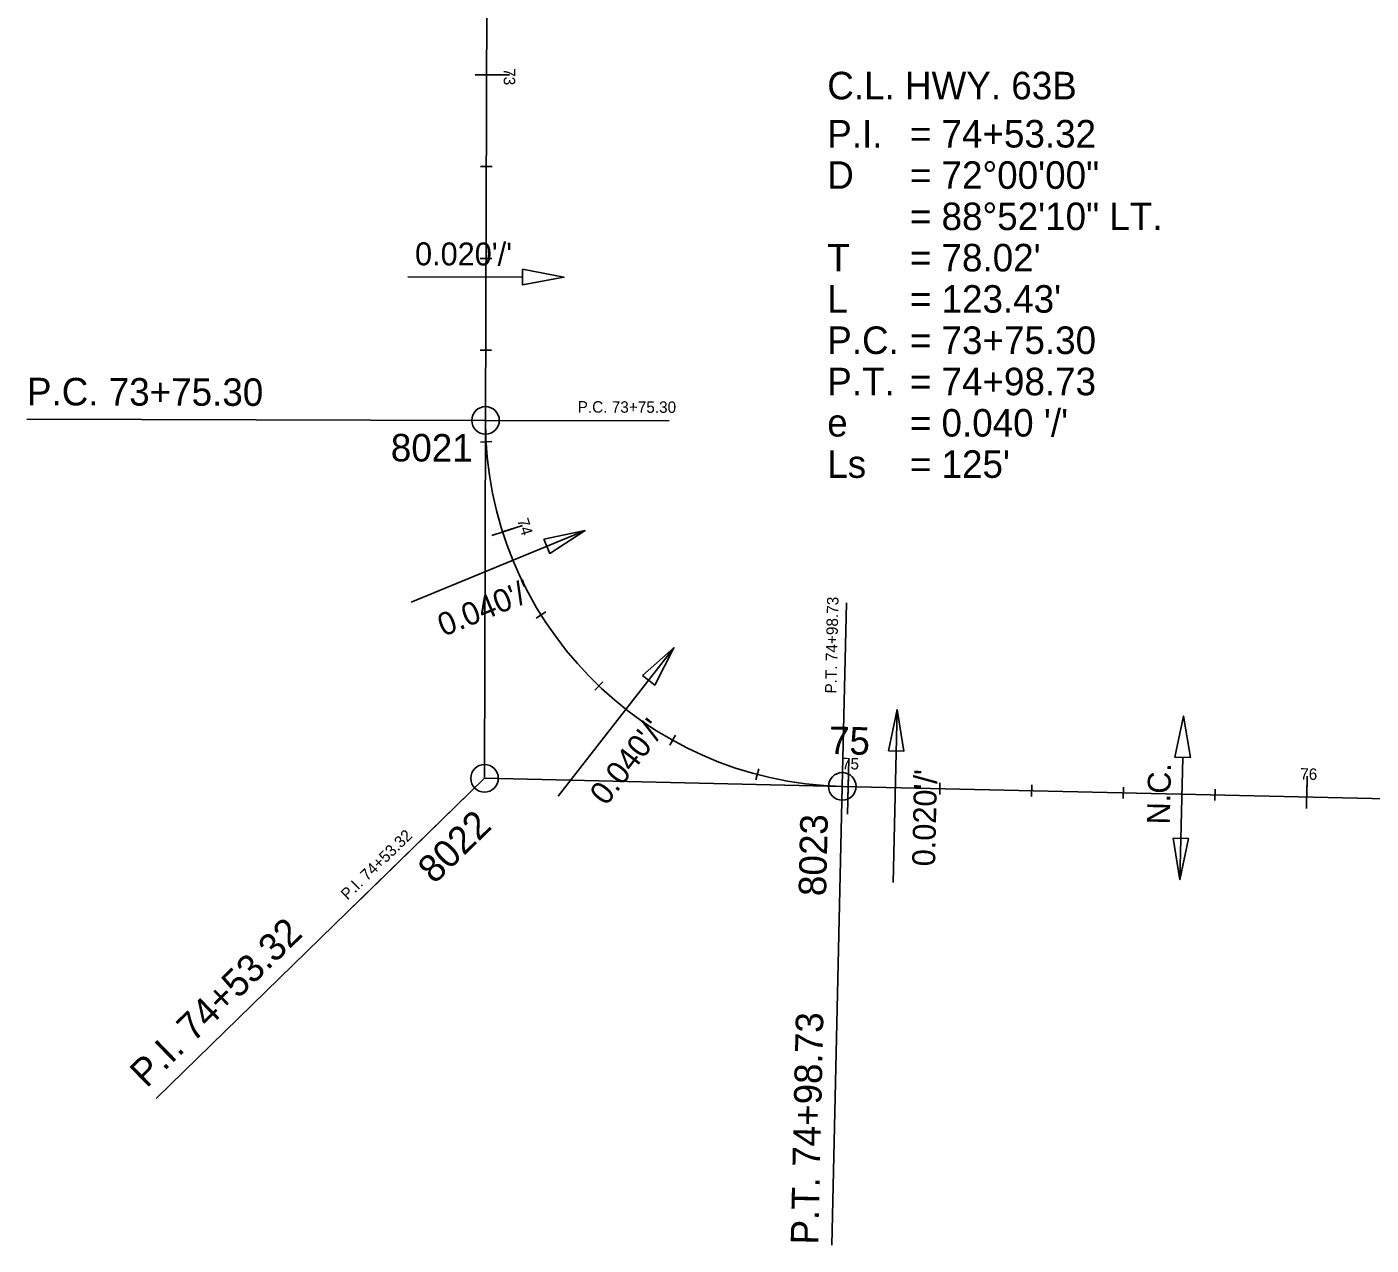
# Model space of a CAD drawing. Extents: x 1708585 to 1714116, y 541444 to 545437.
# Drawn here: x 1711889.1 to 1712182.2, y 543264.6 to 543530.1 of the extents above; entities that cross this region are included whole.
import ezdxf

# ---------------------------------------------------------------- set-up
doc = ezdxf.new("R2010")
doc.units = 0
for name, color, linetype in [('CL_Highway_2', 7, 'Continuous'), ('CL_Highway_2_40_PText', 7, 'Continuous'), ('CL_Highway_2_40_Sta', 7, 'Continuous'), ('CL_Highway_2_PText', 7, 'Continuous'), ('CL_Highway_2_Sta', 7, 'Continuous'), ('CL_Highway_2_Tangent', 7, 'Continuous'), ('CurveData_100', 7, 'Continuous'), ('Point_CL_Highway_2', 7, 'Continuous'), ('Point_Number', 7, 'Continuous'), ('R_SE_Slope', 7, 'Continuous')]:
    doc.layers.add(name, color=color, linetype=linetype)

msp = doc.modelspace()

# ---------------------------------------------------------------- linework, layer by layer
at = {"layer": 'CL_Highway_2'}
for p, q in [((1711989.93, 543735.39), (1711989.1, 543444.38)), ((1712066.88, 543364.6), (1712214.97, 543361.25))]:
    msp.add_line(p, q, dxfattribs=at)
msp.add_arc((1712068.68, 543444.15), 79.58, 179.8364, 268.7057, dxfattribs=at)
at = {"layer": 'CL_Highway_2_40_PText'}
for points in [[(1711989.1, 543444.38), (1712029.1, 543444.27)], [(1712066.88, 543364.6), (1712067.78, 543404.59)], [(1711988.88, 543366.36), (1711960.24, 543338.44)]]:
    msp.add_lwpolyline(points, dxfattribs=at)
at = {"layer": 'CL_Highway_2_40_Sta'}
for points in [[(1711991.81, 543519.67), (1711986.81, 543519.69)], [(1711990.51, 543499.68), (1711988.01, 543499.69)], [(1711990.45, 543479.68), (1711987.95, 543479.69)], [(1711990.39, 543459.68), (1711987.89, 543459.69)], [(1711990.47, 543439.75), (1711987.98, 543439.61)], [(1711995.22, 543420.82), (1711990.45, 543419.31)], [(1712002.27, 543402.62), (1712000.15, 543401.3)], [(1712014.68, 543387.41), (1712012.96, 543385.6)], [(1712030.49, 543375.77), (1712029.27, 543373.58)], [(1712048.69, 543368.42), (1712048.06, 543366)], [(1712068.2, 543367.07), (1712068.09, 543362.07)], [(1712088.17, 543365.37), (1712088.11, 543362.87)], [(1712108.17, 543364.91), (1712108.11, 543362.41)], [(1712168.18, 543364.81), (1712168.07, 543359.81)], [(1712128.16, 543364.46), (1712128.1, 543361.96)], [(1712148.16, 543364.01), (1712148.1, 543361.51)]]:
    msp.add_lwpolyline(points, dxfattribs=at)
at = {"layer": 'CL_Highway_2_PText'}
for points in [[(1711989.1, 543444.38), (1711889.1, 543444.67)], [(1711988.88, 543366.36), (1711917.27, 543296.55)], [(1712066.88, 543364.6), (1712064.62, 543264.62)]]:
    msp.add_lwpolyline(points, dxfattribs=at)
at = {"layer": 'CL_Highway_2_Sta'}
for p, q in [((1711994.31, 543519.67), (1711989.31, 543519.68)), ((1712068.28, 543370.57), (1712068.01, 543358.57))]:
    msp.add_line(p, q, dxfattribs=at)
for points in [[(1711997.12, 543421.43), (1711992.83, 543420.07)], [(1712168.22, 543366.81), (1712168.12, 543362.31)]]:
    msp.add_lwpolyline(points, dxfattribs=at)
at = {"layer": 'CL_Highway_2_Tangent'}
msp.add_lwpolyline([(1711989.1, 543444.38), (1711988.88, 543366.36), (1712066.88, 543364.6)], dxfattribs=at)
at = {"layer": 'Point_CL_Highway_2'}
for centre in [(1711989.1, 543444.38), (1711988.88, 543366.36), (1712066.88, 543364.6)]:
    msp.add_circle(centre, 3, dxfattribs=at)
at = {"layer": 'R_SE_Slope'}
for p, q in [((1711972.19, 543475.68), (1711997.19, 543475.61)), ((1711972.87, 543404.79), (1712010.79, 543420.37)), ((1712004.95, 543362.5), (1712030.17, 543394.82)), ((1712077.97, 543343.63), (1712078.82, 543381.33)), ((1712140.5, 543344.26), (1712141.1, 543370.92))]:
    msp.add_line(p, q, dxfattribs=at)
for points in [[(1711997.19, 543477.3), (1711997.18, 543473.92), (1712006.19, 543475.58)], [(1712001.83, 543418.51), (1712003.11, 543415.39), (1712010.79, 543420.37)], [(1712023.31, 543388.77), (1712025.97, 543386.69), (1712030.17, 543394.82)], [(1712076.93, 543372.37), (1712080.3, 543372.3), (1712078.82, 543381.33)], [(1712139.41, 543370.96), (1712142.79, 543370.88), (1712141.3, 543379.92)], [(1712142.39, 543353.22), (1712139.01, 543353.29), (1712140.5, 543344.26)]]:
    msp.add_lwpolyline(points, close=True, dxfattribs=at)

# ---------------------------------------------------------------- texts
at = {"layer": 'CL_Highway_2_40_PText'}
for s, rotation, p in [('P.C. 73+75.30', 359.8364, (1712009.18, 543446.07)), ('P.T. 74+98.73', 88.7057, (1712065.59, 543384.82)), ('P.I. 74+53.32', 44.2711, (1711959.01, 543339.69))]:
    msp.add_text(s, height=2.5, rotation=rotation, dxfattribs=at).set_placement(p)
at = {"layer": 'CL_Highway_2_40_Sta'}
for s, rotation, p in [('73', 269.8364, (1711993.07, 543521.14)), ('74', 287.6196, (1711995.96, 543422.6)), ('75', 358.7057, (1712066.77, 543368.35)), ('76', 358.7057, (1712166.69, 543366.09))]:
    msp.add_text(s, height=2.5, rotation=rotation, dxfattribs=at).set_placement(p)
at = {"layer": 'CL_Highway_2_PText'}
for s, rotation, p in [('P.C. 73+75.30', 359.8364, (1711889.11, 543447.67)), ('P.I. 74+53.32', 44.2711, (1711915.18, 543298.7)), ('P.T. 74+98.73', 88.7057, (1712061.62, 543264.69))]:
    msp.add_text(s, height=6, rotation=rotation, dxfattribs=at).set_placement(p)
at = {"layer": 'CL_Highway_2_Sta'}
msp.add_text('75', height=6, rotation=358.7057, dxfattribs=at).set_placement((1712063.91, 543371.67))
at = {"layer": 'CurveData_100'}
for s, p in [('C.L. HWY. 63B', (1712063.6, 543514.35)), ('P.I.', (1712063.6, 543503.85)), ('= 74+53.32', (1712081.6, 543503.85)), ('D', (1712063.6, 543494.85)), ('= 72%%d00\'00"', (1712081.6, 543494.85)), ('= 88%%d52\'10" LT.', (1712081.6, 543485.85)), ('T', (1712063.6, 543476.85)), ("= 78.02'", (1712081.6, 543476.85)), ('L', (1712063.6, 543467.85)), ("= 123.43'", (1712081.6, 543467.85)), ('P.C.', (1712063.6, 543458.85)), ('= 73+75.30', (1712081.6, 543458.85)), ('P.T.', (1712063.6, 543449.85)), ('= 74+98.73', (1712081.6, 543449.85)), ("= 0.040 '/'", (1712081.6, 543440.85)), ('e', (1712063.6, 543440.85)), ('Ls', (1712063.6, 543431.85)), ("= 125'", (1712081.6, 543431.85))]:
    msp.add_text(s, height=6, dxfattribs=at).set_placement(p)
at = {"layer": 'Point_Number'}
for s, rotation, p in [('8021', 359.8364, (1711968.44, 543435.44)), ('8022', 44.2711, (1711977.95, 543343.14)), ('8023', 88.7057, (1712063.34, 543340.64))]:
    msp.add_text(s, height=6, rotation=rotation, dxfattribs=at).set_placement(p)
at = {"layer": 'R_SE_Slope'}
for s, rotation, p in [("0.020'/'", 359.8364, (1711973.72, 543478.18)), ("0.040'/'", 22.3356, (1711979.95, 543397.18)), ("0.040'/'", 52.0284, (1712015.37, 543360.18)), ("0.020'/'", 88.7057, (1712087.09, 543347.14)), ('N.C.', 88.7057, (1712138.27, 543356.27))]:
    msp.add_text(s, height=5, rotation=rotation, dxfattribs=at).set_placement(p)

doc.saveas('drawing.dxf')
